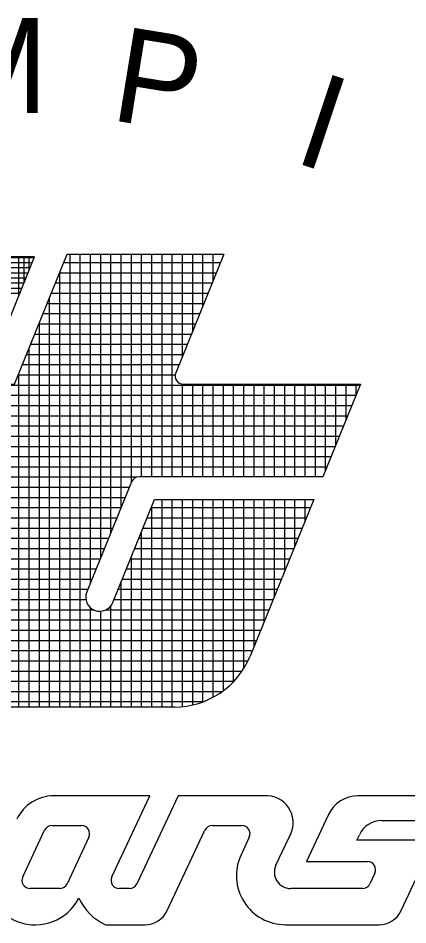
# Model space of a CAD drawing. Extents: x 0 to 3.5, y -0.08 to 2.5.
# Drawn here: x 3.314 to 3.3448, y 2.3382 to 2.4098 of the extents above; entities that cross this region are included whole.
import ezdxf

# ---------------------------------------------------------------- set-up
doc = ezdxf.new("R2010")
doc.units = 0
doc.layers.add('A-ANNO-TEXT', color=7, linetype='Continuous')
doc.layers.add('Default', color=7, linetype='Continuous')

msp = doc.modelspace()

# ---------------------------------------------------------------- linework, layer by layer
at = {"layer": 'A-ANNO-TEXT'}
for p, q in [((3.2922269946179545, 2.390869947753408), (3.3153235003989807, 2.3908699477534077)), ((3.3141016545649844, 2.387858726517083), (3.3141016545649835, 2.3909033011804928)), ((3.314504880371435, 2.3888524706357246), (3.3145048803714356, 2.390903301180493)), ((3.3149081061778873, 2.389846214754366), (3.314908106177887, 2.3909033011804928)), ((3.315311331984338, 2.3908399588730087), (3.315311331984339, 2.390903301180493)), ((3.3181339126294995, 2.3553674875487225), (3.3181339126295, 2.391129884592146)), ((3.3189403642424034, 2.355367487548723), (3.3189403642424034, 2.391129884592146)), ((3.319746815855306, 2.3651808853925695), (3.3197468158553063, 2.391129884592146)), ((3.3205532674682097, 2.367168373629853), (3.3205532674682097, 2.391129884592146)), ((3.3213597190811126, 2.369155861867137), (3.3213597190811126, 2.391129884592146)), ((3.322166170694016, 2.3711433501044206), (3.3221661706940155, 2.391129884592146)), ((3.322972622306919, 2.3731308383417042), (3.32297262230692, 2.3911298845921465)), ((3.3237790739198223, 2.373554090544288), (3.323779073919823, 2.391129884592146)), ((3.3245855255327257, 2.373554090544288), (3.3245855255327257, 2.391129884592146)), ((3.3253919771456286, 2.373554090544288), (3.3253919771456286, 2.391129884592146)), ((3.3261984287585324, 2.373554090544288), (3.3261984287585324, 2.391129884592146)), ((3.327004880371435, 2.383068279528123), (3.3270048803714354, 2.391129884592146)), ((3.327811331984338, 2.3850557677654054), (3.3278113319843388, 2.3911298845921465)), ((3.3286177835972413, 2.387043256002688), (3.328617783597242, 2.3911298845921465)), ((3.329424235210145, 2.389030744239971), (3.329424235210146, 2.3911298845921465)), ((3.3302306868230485, 2.3910182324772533), (3.330230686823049, 2.391129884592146)), ((3.2905492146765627, 2.390466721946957), (3.3151598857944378, 2.3904667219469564)), ((3.3176426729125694, 2.3904667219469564), (3.330006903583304, 2.3904667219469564)), ((3.2890750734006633, 2.389660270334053), (3.314832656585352, 2.389660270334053)), ((3.289699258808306, 2.3900634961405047), (3.314996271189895, 2.3900634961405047)), ((3.3173154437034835, 2.3896602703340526), (3.3296796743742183, 2.3896602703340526)), ((3.3173274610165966, 2.3553674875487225), (3.3173274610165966, 2.389689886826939)), ((3.2881657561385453, 2.38885381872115), (3.3145054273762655, 2.3888538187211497)), ((3.288577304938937, 2.389257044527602), (3.3146690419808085, 2.389257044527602)), ((3.3169882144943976, 2.3888538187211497), (3.329352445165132, 2.3888538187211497)), ((3.287525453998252, 2.3880473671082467), (3.314178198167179, 2.3880473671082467)), ((3.287819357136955, 2.388450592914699), (3.3143418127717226, 2.388450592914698)), ((3.3166609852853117, 2.388047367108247), (3.329025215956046, 2.3880473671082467)), ((3.3163337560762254, 2.387240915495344), (3.3286979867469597, 2.387240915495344)), ((3.316521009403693, 2.3553674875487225), (3.316521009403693, 2.387702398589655)), ((3.3160065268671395, 2.38643446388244), (3.3283707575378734, 2.38643446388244)), ((3.315679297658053, 2.385628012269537), (3.3280435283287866, 2.385628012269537)), ((3.3157145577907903, 2.3553674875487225), (3.31571455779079, 2.385714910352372)), ((3.3153520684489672, 2.384821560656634), (3.3277162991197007, 2.3848215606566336)), ((3.3149081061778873, 2.3553674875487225), (3.314908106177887, 2.3837274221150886)), ((3.315024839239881, 2.3840151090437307), (3.3273890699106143, 2.3840151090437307)), ((3.314697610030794, 2.383208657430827), (3.3270618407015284, 2.3832086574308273)), ((3.3143703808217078, 2.382402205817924), (3.3267346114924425, 2.3824022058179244)), ((3.3140431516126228, 2.381595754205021), (3.3264280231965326, 2.3815957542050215)), ((3.3141016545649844, 2.3553674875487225), (3.3141016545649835, 2.381739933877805)), ((3.2994815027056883, 2.380789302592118), (3.3410220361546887, 2.380789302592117)), ((3.327004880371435, 2.373554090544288), (3.327004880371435, 2.3808626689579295)), ((3.3278113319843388, 2.373554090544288), (3.3278113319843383, 2.3808596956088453)), ((3.3286177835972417, 2.373554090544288), (3.3286177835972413, 2.380859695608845)), ((3.329424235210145, 2.3735540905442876), (3.329424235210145, 2.380859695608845)), ((3.330230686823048, 2.373554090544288), (3.330230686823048, 2.3808596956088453)), ((3.331037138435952, 2.373554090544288), (3.3310371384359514, 2.3808596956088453)), ((3.3318435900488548, 2.373554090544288), (3.3318435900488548, 2.380859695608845)), ((3.332650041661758, 2.373554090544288), (3.332650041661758, 2.3808596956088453)), ((3.333456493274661, 2.373554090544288), (3.333456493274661, 2.3808596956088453)), ((3.334262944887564, 2.373554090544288), (3.334262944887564, 2.3808596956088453)), ((3.335069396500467, 2.3735540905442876), (3.335069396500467, 2.3808596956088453)), ((3.3358758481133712, 2.373554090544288), (3.3358758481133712, 2.3808596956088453)), ((3.336682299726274, 2.373554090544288), (3.3366822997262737, 2.3808596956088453)), ((3.3374887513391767, 2.373554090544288), (3.337488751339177, 2.3808596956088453)), ((3.33829520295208, 2.374069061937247), (3.33829520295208, 2.3808596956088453)), ((3.3391016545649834, 2.37605655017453), (3.3391016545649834, 2.3808596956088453)), ((3.3399081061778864, 2.3780440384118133), (3.3399081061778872, 2.3808596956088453)), ((3.3407145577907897, 2.380031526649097), (3.3407145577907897, 2.3808596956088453)), ((3.299154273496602, 2.3799828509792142), (3.3406948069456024, 2.3799828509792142)), ((3.2988270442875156, 2.3791763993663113), (3.3403675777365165, 2.3791763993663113)), ((3.29849981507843, 2.378369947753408), (3.3400403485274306, 2.3783699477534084)), ((3.298172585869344, 2.3775634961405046), (3.3397131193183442, 2.3775634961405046)), ((3.297845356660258, 2.3767570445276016), (3.339385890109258, 2.3767570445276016)), ((3.297518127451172, 2.3759505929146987), (3.339058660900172, 2.3759505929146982)), ((3.297190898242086, 2.3751441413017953), (3.3387314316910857, 2.3751441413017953)), ((3.2968636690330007, 2.374337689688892), (3.338404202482, 2.374337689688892)), ((3.310770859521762, 2.373531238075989), (3.3234086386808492, 2.3735312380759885)), ((3.3104436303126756, 2.3727247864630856), (3.3228078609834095, 2.3727247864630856)), ((3.3101164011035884, 2.371918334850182), (3.3224806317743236, 2.3719183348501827)), ((3.3253919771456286, 2.355367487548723), (3.3253919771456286, 2.3717609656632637)), ((3.3261984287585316, 2.355367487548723), (3.3261984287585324, 2.371760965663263)), ((3.3270048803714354, 2.3553995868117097), (3.327004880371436, 2.3717609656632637)), ((3.3278113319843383, 2.355532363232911), (3.3278113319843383, 2.3717609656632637)), ((3.3286177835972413, 2.355774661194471), (3.3286177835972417, 2.371760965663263)), ((3.329424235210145, 2.356140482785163), (3.329424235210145, 2.3717609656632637)), ((3.330230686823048, 2.3566560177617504), (3.330230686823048, 2.3717609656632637)), ((3.331037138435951, 2.357373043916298), (3.331037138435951, 2.371760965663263)), ((3.3318435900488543, 2.358416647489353), (3.3318435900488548, 2.3717609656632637)), ((3.3326500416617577, 2.3601566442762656), (3.332650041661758, 2.371760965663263)), ((3.3334564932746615, 2.3621441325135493), (3.3334564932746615, 2.3717609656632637)), ((3.334262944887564, 2.3641316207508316), (3.334262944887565, 2.3717609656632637)), ((3.335069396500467, 2.3661191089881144), (3.3350693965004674, 2.371760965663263)), ((3.3358758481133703, 2.368106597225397), (3.3358758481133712, 2.371760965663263)), ((3.3366822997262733, 2.3700940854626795), (3.3366822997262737, 2.371760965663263)), ((3.3097891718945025, 2.371111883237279), (3.3221534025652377, 2.3711118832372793)), ((3.324544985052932, 2.371111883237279), (3.337095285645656, 2.3711118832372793)), ((3.3245855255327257, 2.3553674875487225), (3.3245855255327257, 2.371211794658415)), ((3.309461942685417, 2.370305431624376), (3.3218261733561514, 2.370305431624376)), ((3.3242177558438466, 2.370305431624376), (3.336768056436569, 2.370305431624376)), ((3.30913471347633, 2.3694989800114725), (3.321498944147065, 2.3694989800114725)), ((3.32389052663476, 2.369498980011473), (3.336440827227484, 2.369498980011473)), ((3.308807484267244, 2.3686925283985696), (3.321171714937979, 2.3686925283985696)), ((3.3235632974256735, 2.3686925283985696), (3.3361135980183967, 2.3686925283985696)), ((3.3237790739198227, 2.3553674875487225), (3.3237790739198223, 2.369224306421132)), ((3.3084802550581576, 2.3678860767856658), (3.320844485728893, 2.367886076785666)), ((3.323236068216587, 2.3678860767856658), (3.3357863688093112, 2.367886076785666)), ((3.322972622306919, 2.3553674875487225), (3.322972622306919, 2.3672368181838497)), ((3.3081530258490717, 2.3670796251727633), (3.320517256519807, 2.367079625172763)), ((3.3229088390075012, 2.367079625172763), (3.3354591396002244, 2.367079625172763)), ((3.307825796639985, 2.36627317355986), (3.3201900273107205, 2.36627317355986)), ((3.322581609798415, 2.36627317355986), (3.335131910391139, 2.36627317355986)), ((3.3074985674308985, 2.365466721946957), (3.3198627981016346, 2.365466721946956)), ((3.322166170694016, 2.3553674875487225), (3.3221661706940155, 2.3652493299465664)), ((3.3222543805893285, 2.365466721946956), (3.3348046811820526, 2.365466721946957)), ((3.307171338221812, 2.364660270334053), (3.3195355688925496, 2.3646602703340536)), ((3.3219271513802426, 2.364660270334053), (3.3344774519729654, 2.364660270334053)), ((3.3068441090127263, 2.36385381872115), (3.319384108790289, 2.36385381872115)), ((3.3215999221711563, 2.36385381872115), (3.33415022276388, 2.36385381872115)), ((3.3065168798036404, 2.3630473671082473), (3.3199736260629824, 2.363047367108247)), ((3.3197468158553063, 2.3553674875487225), (3.3197468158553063, 2.3632011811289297)), ((3.3205532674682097, 2.3553674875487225), (3.3205532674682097, 2.362928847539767)), ((3.3209810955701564, 2.363047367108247), (3.3338229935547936, 2.363047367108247)), ((3.321359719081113, 2.3553674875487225), (3.3213597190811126, 2.363364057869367)), ((3.306189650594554, 2.3622409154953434), (3.3334957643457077, 2.3622409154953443)), ((3.3058624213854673, 2.3614344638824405), (3.333168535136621, 2.36143446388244)), ((3.3055351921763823, 2.3606280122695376), (3.332841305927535, 2.360628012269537)), ((3.3052079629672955, 2.3598215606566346), (3.332514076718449, 2.359821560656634)), ((3.3048807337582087, 2.359015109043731), (3.3321725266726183, 2.359015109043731)), ((3.3046653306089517, 2.3582086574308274), (3.331708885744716, 2.3582086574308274)), ((3.3047105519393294, 2.3574022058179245), (3.3310646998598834, 2.3574022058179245)), ((3.305034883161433, 2.356595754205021), (3.330148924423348, 2.3565957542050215)), ((3.305818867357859, 2.3557893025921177), (3.3286566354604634, 2.3557893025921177))]:
    msp.add_line(p, q, dxfattribs=at)
for points in [[(3.2989933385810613, 2.38277387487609), (3.3120384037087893, 2.38277387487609), (3.3153370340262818, 2.390903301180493), (3.2928821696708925, 2.3909033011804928)], [(3.304841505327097, 2.3589184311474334), (3.310780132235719, 2.373554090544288), (3.2965457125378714, 2.373554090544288), (3.2995100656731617, 2.380859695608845), (3.31374448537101, 2.380859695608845), (3.3179117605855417, 2.391129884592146), (3.3302759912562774, 2.391129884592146), (3.3264689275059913, 2.381747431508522)], [(3.327066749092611, 2.380859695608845), (3.341050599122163, 2.3808596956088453), (3.338086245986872, 2.373554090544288), (3.323578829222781, 2.373554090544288)], [(3.3229810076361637, 2.3731515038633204), (3.3194506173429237, 2.3644509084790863)], [(3.3215041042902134, 2.363617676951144), (3.324808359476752, 2.371760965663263), (3.3373586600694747, 2.371760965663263), (3.3323403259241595, 2.3593933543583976)], [(3.3263621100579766, 2.3553674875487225), (3.307232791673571, 2.3553674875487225)], [(3.321423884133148, 2.341954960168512), (3.324423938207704, 2.3483572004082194), (3.3168547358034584, 2.3483572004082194)], [(3.3214238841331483, 2.3419549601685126), (3.324423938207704, 2.3483572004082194), (3.3168547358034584, 2.34835720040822)], [(3.3337509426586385, 2.3483572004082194), (3.3266631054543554, 2.3483572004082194), (3.323406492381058, 2.3414074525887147)], [(3.333750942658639, 2.34835720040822), (3.3266631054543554, 2.3483572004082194), (3.323406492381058, 2.3414074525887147)], [(3.347589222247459, 2.3463971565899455), (3.348507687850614, 2.3483572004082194), (3.3408649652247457, 2.3483572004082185)], [(3.3427133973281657, 2.3463971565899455), (3.3475363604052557, 2.3463971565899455), (3.348507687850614, 2.3483572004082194), (3.3408649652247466, 2.3483572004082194)], [(3.338528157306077, 2.3468715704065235), (3.336788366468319, 2.343158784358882), (3.341601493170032, 2.343158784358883)], [(3.338528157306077, 2.3468715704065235), (3.336788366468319, 2.343158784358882), (3.341601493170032, 2.343158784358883)], [(3.3167024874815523, 2.346001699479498), (3.319036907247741, 2.346001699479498)], [(3.316702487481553, 2.3460016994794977), (3.319036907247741, 2.346001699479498)], [(3.329355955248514, 2.346001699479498), (3.3316903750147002, 2.346001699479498)], [(3.329355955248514, 2.346001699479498), (3.3316903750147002, 2.346001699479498)], [(3.3427133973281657, 2.3463971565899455), (3.3475363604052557, 2.3463971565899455)], [(3.314396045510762, 2.341954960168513), (3.316118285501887, 2.3456302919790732)], [(3.314396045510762, 2.341954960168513), (3.316118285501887, 2.3456302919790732)], [(3.3196211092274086, 2.3450827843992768), (3.3178988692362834, 2.341407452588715)], [(3.3196211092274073, 2.3450827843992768), (3.3178988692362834, 2.341407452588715)], [(3.325801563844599, 2.3392917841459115), (3.328771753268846, 2.3456302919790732)], [(3.325801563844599, 2.3392917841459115), (3.328771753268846, 2.3456302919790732)], [(3.3322745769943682, 2.3450827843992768), (3.3316224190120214, 2.3436910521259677)], [(3.332274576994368, 2.345082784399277), (3.3316224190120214, 2.343691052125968)], [(3.334375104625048, 2.342873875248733), (3.3354101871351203, 2.3450827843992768)], [(3.3343751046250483, 2.342873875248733), (3.3354101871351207, 2.345082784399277)], [(3.344259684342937, 2.3392917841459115), (3.3468693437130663, 2.3448609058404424), (3.3407630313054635, 2.344860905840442), (3.340960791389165, 2.3452829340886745)], [(3.344259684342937, 2.3392917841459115), (3.3468693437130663, 2.3448609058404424), (3.3407630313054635, 2.344860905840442), (3.340960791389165, 2.3452829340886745)], [(3.342185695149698, 2.342239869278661), (3.3417956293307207, 2.341407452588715)], [(3.342185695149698, 2.342239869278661), (3.341795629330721, 2.3414074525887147)], [(3.3173146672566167, 2.341036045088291), (3.3149802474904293, 2.3410360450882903)], [(3.3173146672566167, 2.3410360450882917), (3.3149802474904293, 2.3410360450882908)], [(3.322822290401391, 2.3410360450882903), (3.3220080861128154, 2.3410360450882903)], [(3.322822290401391, 2.3410360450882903), (3.3220080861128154, 2.3410360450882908)], [(3.341211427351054, 2.3410360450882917), (3.3355435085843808, 2.3410360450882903)], [(3.341211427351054, 2.3410360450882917), (3.335543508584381, 2.3410360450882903)], [(3.3209213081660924, 2.33817756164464), (3.3240489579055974, 2.33817756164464)], [(3.3209213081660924, 2.33817756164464), (3.3240489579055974, 2.33817756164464)], [(3.3351276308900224, 2.33817756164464), (3.3425070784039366, 2.33817756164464)], [(3.3351276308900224, 2.33817756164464), (3.3425070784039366, 2.3381775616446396)]]:
    msp.add_lwpolyline(points, dxfattribs=at)
for centre, radius, start, end in [((3.3270667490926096, 2.3815048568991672), 0.0006451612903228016, 157.91444604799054, 270.00000000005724), ((3.3235788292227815, 2.3729089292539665), 0.0006451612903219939, 90.0000000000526, 157.91444604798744), ((3.3204773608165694, 2.3640342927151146), 0.0011080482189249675, 157.9144460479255, 337.91444604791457), ((3.3263621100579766, 2.3618191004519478), 0.006451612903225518, 269.9999999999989, 337.9144460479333), ((3.316854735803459, 2.345131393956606), 0.0032258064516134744, 90.00000000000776, 154.89247364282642), ((3.316854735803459, 2.345131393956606), 0.0032258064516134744, 90.00000000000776, 154.89247364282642), ((3.33360729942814, 2.3462268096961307), 0.0021352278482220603, 327.60276482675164, 86.14262648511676), ((3.33360729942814, 2.3462268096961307), 0.0021352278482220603, 327.60276482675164, 86.14262648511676), ((3.3408649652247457, 2.345776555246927), 0.002580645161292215, 89.99999999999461, 154.89247364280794), ((3.3408649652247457, 2.345776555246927), 0.002580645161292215, 89.99999999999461, 154.89247364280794), ((3.316702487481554, 2.3453565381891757), 0.0006451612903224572, 90.00000000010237, 154.89247364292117), ((3.316702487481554, 2.3453565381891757), 0.0006451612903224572, 90.00000000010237, 154.89247364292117), ((3.319036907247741, 2.345356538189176), 0.00064516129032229, 334.8924736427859, 90), ((3.319036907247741, 2.345356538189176), 0.00064516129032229, 334.8924736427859, 90), ((3.3293559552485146, 2.3453565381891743), 0.0006451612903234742, 90.0000000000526, 154.89247364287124), ((3.3293559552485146, 2.3453565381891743), 0.0006451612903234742, 90.0000000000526, 154.89247364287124), ((3.3316903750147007, 2.3453565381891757), 0.0006451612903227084, 334.8924736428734, 90.00000000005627), ((3.3316903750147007, 2.3453565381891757), 0.0006451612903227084, 334.8924736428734, 90.00000000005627), ((3.3427133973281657, 2.3444616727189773), 0.0019354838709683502, 89.99999999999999, 154.892473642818), ((3.3427133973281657, 2.3444616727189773), 0.0019354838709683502, 89.99999999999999, 154.892473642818), ((3.335127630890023, 2.342048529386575), 0.003870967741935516, 154.8924736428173, 269.99999999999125), ((3.335127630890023, 2.342048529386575), 0.003870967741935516, 154.8924736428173, 269.99999999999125), ((3.3355435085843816, 2.342326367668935), 0.0012903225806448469, 154.8924736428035, 269.9999999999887), ((3.3355435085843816, 2.342326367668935), 0.0012903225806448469, 154.8924736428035, 269.9999999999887), ((3.341601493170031, 2.3425136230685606), 0.0006451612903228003, 334.89247364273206, 89.9999999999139), ((3.341601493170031, 2.3425136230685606), 0.0006451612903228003, 334.89247364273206, 89.9999999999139), ((3.3151203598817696, 2.341430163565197), 0.0032258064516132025, 154.8924736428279, 250.39567383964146), ((3.3151203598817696, 2.341430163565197), 0.0032258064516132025, 154.8924736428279, 250.39567383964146), ((3.314980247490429, 2.3416812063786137), 0.000645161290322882, 154.89247364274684, 270.0000000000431), ((3.314980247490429, 2.3416812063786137), 0.000645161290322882, 154.89247364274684, 270.0000000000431), ((3.3173146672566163, 2.341681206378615), 0.0006451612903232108, 270.0000000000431, 334.89247364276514), ((3.3173146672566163, 2.341681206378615), 0.0006451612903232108, 270.0000000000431, 334.89247364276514), ((3.3220080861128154, 2.3416812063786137), 0.0006451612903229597, 154.8924736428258, 270.00000000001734), ((3.3220080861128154, 2.3416812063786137), 0.0006451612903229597, 154.8924736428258, 270.00000000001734), ((3.3228222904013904, 2.341681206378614), 0.0006451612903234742, 270.0000000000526, 334.89247364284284), ((3.3228222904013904, 2.341681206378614), 0.0006451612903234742, 270.0000000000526, 334.89247364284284), ((3.3412114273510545, 2.3416812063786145), 0.0006451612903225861, 269.9999999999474, 334.8924736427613), ((3.3412114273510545, 2.3416812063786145), 0.0006451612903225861, 269.9999999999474, 334.8924736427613), ((3.3153566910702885, 2.3420937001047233), 0.003930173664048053, 250.39567384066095, 332.2908433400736), ((3.3153566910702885, 2.3420937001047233), 0.003930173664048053, 250.39567384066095, 332.2908433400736), ((3.3227220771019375, 2.3420604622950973), 0.004280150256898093, 204.7839320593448, 245.11959164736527), ((3.3227220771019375, 2.3420604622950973), 0.004280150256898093, 204.7839320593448, 245.11959164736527), ((3.3240489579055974, 2.3401130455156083), 0.001935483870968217, 270.0000000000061, 334.8924736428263), ((3.3240489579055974, 2.3401130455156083), 0.001935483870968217, 270.0000000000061, 334.8924736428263), ((3.342507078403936, 2.340113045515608), 0.0019354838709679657, 270.00000000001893, 334.89247364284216), ((3.342507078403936, 2.340113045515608), 0.0019354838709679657, 270.00000000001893, 334.89247364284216)]:
    msp.add_arc(centre, radius, start, end, dxfattribs=at)

# ---------------------------------------------------------------- texts
at = {"layer": 'Default'}
for s, height, rotation, p in [('M', 0.007480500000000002, 0.04850433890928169, (3.3080632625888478, 2.4022788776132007)), ('P', 0.007480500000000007, 350.77515673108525, (3.3211972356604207, 2.401745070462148)), ('I', 0.0074805, 341.5018091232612, (3.3356030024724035, 2.3984686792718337))]:
    msp.add_text(s, height=height, rotation=rotation, dxfattribs=at).set_placement(p)

doc.saveas('drawing.dxf')
